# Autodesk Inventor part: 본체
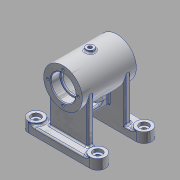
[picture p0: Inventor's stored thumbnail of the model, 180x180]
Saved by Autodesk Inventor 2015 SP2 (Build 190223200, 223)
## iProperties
Created: 2015-11
Part Number: 본체
Material: 알루미늄 6061
Document SubType Name: Modeling
Designer: AMC
Density: 2.7 g/cm^3
Appearance: 알루미늄 - 평지
Author: AMC
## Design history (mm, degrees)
sketch "스케치1"
  geometry: L1 (-40, 40)-(40, 40); L2 (40, 40)-(40, 20); L3 (40, 20)-(-40, 20); L4 (-40, 20)-(-40, 40); L5 (-40, -40)-(40, -40); L6 (40, -40)-(40, -20); L7 (40, -20)-(-40, -20); L8 (-40, -20)-(-40, -40); L9 (-5, -20)-(5, -20); L10 (5, -20)-(5, 20); L11 (5, 20)-(-5, 20); L12 (-5, 20)-(-5, -20); L13 (-5, -20)-(5, 20); L14 (5, -20)-(-5, 20); C1 r 10 at (40, -30); 6 further points
  constraints: 28 end point, 10 midpoint, 6 parallel, 3 horizontal, 3 perpendicular, 3 vertical alignment, 1 centre point, 1 tangent, 6 other
  dimensions: "d8" = 80 distance of L2.end L3.end; "d9" = 20 distance of L1.end L2.end; "d10" = 80 distance of L7.end L6.end; "d11" = 20 distance of L6.end L5.end
extrude "돌출1" new body sketch "스케치1" distance "d14" = 10; taper "d15" = 0 deg
extrude "돌출2" join sketch "스케치1" distance "d16" = 13; taper "d17" = 0 deg
sketch "스케치2"
  geometry: L1 (-25, -20)-(25, -20); L2 (25, -20)-(25, -28); L3 (25, -28)-(-25, -28); L4 (-25, -28)-(-25, -20); L5 (-25, -20)-(25, -28); L6 (25, -20)-(-25, -28); L7 (-25, 28)-(25, 28); L8 (25, 28)-(25, 20); L9 (25, 20)-(-25, 20); L10 (-25, 20)-(-25, 28); L11 (-25, 28)-(25, 20); L12 (25, 28)-(-25, 20); L13 (40, -20)-(-40, -20) reference; L14 (40, 20)-(-40, 20) reference; 5 further points
  constraints: 24 end point, 8 midpoint, 4 parallel, 2 horizontal, 2 perpendicular
  dimensions: "d18" = 50 distance of L2.end L3.end; "d19" = 8 distance of L1.end L2.end; "d20" = 50 distance of L8.end L9.end; "d21" = 8 distance of L7.end L8.end
extrude "돌출3" join sketch "스케치2" distance "d22" = 58; taper "d23" = 0 deg
sketch "스케치3"
  geometry: C1 r 25 at (0, 68); 1 further point
  constraints: 1 centre point
  dimensions: "d24" = 50 diameter of C1
extrude "돌출4" join sketch "스케치3" stored distance "d25" = 70; taper "d26" = 0 deg
sketch "스케치4"
  geometry: C1 r 16 at (0, 0); 1 further point
  constraints: 1 centre point
  dimensions: "d27" = 32 diameter of C1
extrude "돌출5" cut sketch "스케치4" distance "d28" = 12; taper "d29" = 0 deg
sketch "스케치5"
  geometry: C1 r 14 at (0, 0); 1 further point
  constraints: 1 centre point
  dimensions: "d30" = 28 diameter of C1
extrude "돌출6" cut sketch "스케치5" distance "d31" = 2; taper "d32" = 0 deg
sketch "스케치6"
  geometry: C1 r 21 at (0, 68); 1 further point
  constraints: 1 centre point
  dimensions: "d33" = 42 diameter of C1
extrude "돌출7" cut sketch "스케치6" stored distance "d34" = 42; taper "d35" = 0 deg
sketch "스케치7"
  geometry: C1 r 6 at (0, 0); C2 r 3 at (0, 0); 1 further point
  constraints: 2 centre point, 1 coincident
  dimensions: "d36" = 12 diameter of C1; "d37" = 6 diameter of C2
extrude "돌출8" cut sketch "스케치7" distance "d38" = 13; taper "d39" = 0 deg
extrude "돌출9" cut sketch "스케치7" distance "d40" = 4; taper "d41" = 0 deg
sketch "스케치8"
  geometry: L1 (44, -43)-(36, -43); L2 (36, -43)-(36, -23); L3 (36, -23)-(44, -23); L4 (44, -23)-(44, -43); L5 (44, -43)-(36, -23); L6 (36, -43)-(44, -23); A1 r 25 centre (40, -68) between (65, -68) and (15, -68) reference; 4 further points
  constraints: 12 end point, 3 midpoint, 2 coincident, 2 parallel, 1 horizontal, 1 perpendicular, 1 point on circle
  dimensions: "d42" = 8 distance of L2.end L3.end; "d43" = 20 distance of L1.end L2.end
extrude "돌출10" join sketch "스케치8" stored distance "d44" = 4; taper "d45" = 0 deg
chamfer "모따기1" distance "d46" = 1; stored, may be unused: second distance "d47" = 2, angle "d48" = 45 deg
fillet "모깎기1" dims "d49" = 3
fillet "모깎기2" dims "d50" = 0.3
sketch "스케치9"
  geometry: L1 (10, 8.5)-(10, 8.5); L2 (13.5, 12)-(13.5, 28); L3 (10, 31.5)-(10, 31.5); L4 (6.5, 28)-(6.5, 12); L5 (6.5, 8.5)-(13.5, 31.5); L6 (13.5, 8.5)-(6.5, 31.5); L7 (0, 0)-(20, 0); L8 (10, 0)-(10, 40); A1 r 3.5 centre (10, 12) between (10, 8.5) and (13.5, 12); A2 r 3.5 centre (10, 12) between (6.5, 12) and (10, 8.5); A3 r 3.5 centre (10, 28) between (10, 31.5) and (6.5, 28); A4 r 3.5 centre (10, 28) between (13.5, 28) and (10, 31.5); 1 further point
  constraints: 16 end point, 8 point on circle, 8 point on line, 8 tangent, 4 centre point, 4 midpoint, 3 equal radius, 2 horizontal, 2 parallel, 1 perpendicular, 1 vertical
  dimensions: "d51" = 7 distance of L6.end L5.end; "d52" = 23 distance of L5.end L6.start; "d55" = 3.5 radius of A1
extrude "돌출11" cut sketch "스케치9" distance "d56" = 8; taper "d57" = 0 deg
fillet "모깎기3" dims "d58" = 2
fillet "모깎기4" dims "d59" = 2
fillet "모깎기5" dims "d60" = 2
sketch "스케치10"
  geometry: L1 (0, 68)-(0, 96); L2 (0, 68)-(-14, 43.751); 1 further point
  constraints: 4 end point, 1 vertical
  dimensions: "d62" = 28 distance of L1.start L2.end; "d63" = 30 deg angle of L2 L1
node "작업 평면1"
sketch "스케치11"
  geometry: C1 r 5 at (0, 0); 1 further point
  constraints: 1 centre point, 1 coincident
  dimensions: "d64" = 10 diameter of C1
extrude "돌출12" join sketch "스케치11" distance "d65" = 4; taper "d66" = 0 deg
node "작업 평면2"
sketch "스케치12"
  geometry: C1 r 6 at (0, 0); 1 further point
  constraints: 1 centre point
  dimensions: "d67" = 12 diameter of C1
extrude "돌출13" join sketch "스케치12" distance "d68" = 6; taper "d69" = 0 deg
hole "구멍1" diameter "d72" = 4.917; stored, may be unused: countersink angle "d76" = 90 deg, drill point angle "d78" = 118 deg; dims "d73" = 12, "d74" = 4, "d75" = 2, "d77" = 17, "d88" = 10, "d89" = 10
hole "구멍2" diameter "d81" = 4.917; stored, may be unused: countersink angle "d85" = 90 deg, drill point angle "d87" = 118 deg; dims "d79" = 10, "d80" = 10, "d82" = 12, "d83" = 4, "d84" = 2, "d86" = 17
fillet "모깎기6" dims "d90" = 2
fillet "모깎기7" dims "d91" = 2
node "작업 평면3"
sketch "스케치13"
  geometry: L1 (-20.739, -5.707)-(20.739, -5.707); L2 (20.739, -5.707)-(20.739, 5.707); L3 (20.739, 5.707)-(-20.739, 5.707); L4 (-20.739, 5.707)-(-20.739, -5.707); L5 (-20.739, 0)-(20.739, 0); L6 (0, -5.707)-(0, 5.707); L7 (-35, 25)-(-35, -25) reference; 1 further point
  constraints: 5 midpoint, 4 end point, 2 other
  dimensions: "d92" = 35 distance from line of L7 point (0, 0)
feature "엠보싱1" sketch "스케치13" dims "d94" = 0.5, "d95" = 0
sketch "스케치14" dims "d96" = 40
  geometry: 3 further points
  constraints: 1 vertical alignment, 2 other
hole "구멍3" sketch "스케치14" at (0, 20) diameter "d97" = 3.242; stored, may be unused: countersink angle "d101" = 90 deg, drill point angle "d103" = 118 deg; dims "d98" = 8, "d99" = 4, "d100" = 2, "d102" = 10
fillet "모깎기8" dims "d107" = 2
fillet "모깎기9" dims "d108" = 2
fillet "모깎기10" dims "d109" = 2
node "솔리드1"
mirror "대칭1"
mirror "대칭2"
mirror "대칭3"
pattern_circular "원형 패턴1" dims angle "d105" = 360 deg
mirror "대칭4"
